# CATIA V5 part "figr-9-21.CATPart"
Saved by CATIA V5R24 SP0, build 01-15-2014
Part number: Part3
Bounding box of the stored display mesh (mm): x -112 to 0, y -101.683 to 104.654, z -80.304 to 44.557
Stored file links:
  D:\KAVITA\CATIA V5-6R2014 Project_ Kavita\CATIA V5-6R2014_partfiles\Partfiles\c09_catia_v5-6r2014_prt\figr-9-21.CATPart
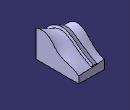
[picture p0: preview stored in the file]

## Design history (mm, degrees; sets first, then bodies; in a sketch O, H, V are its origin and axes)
Set1
  Plane1: type Offset, RefPlane yz-plane, Offset -112
  Plane2: type Offset, RefPlane yz-plane, Offset -63
  Plane3: type Normal, Curve Sketch4, RefPoint vertex of Sketch4
Body1 (main body)
  Sketch1 on yz-plane, origin (0, 0, 0), H (0, 1, 0), V (0, 0, 1)
    spline S1 through (-92.6897, 40.1119) (-30, 30) (10, -10) (60, -30) (97.3103, -50.3041)
    line L1 (97.3103, -50.3041) -> (97.3103, -80.3041)
    line L2 (97.3103, -80.3041) -> (-92.6897, -80.3041)
    line L3 (-92.6897, -80.3041) -> (-92.6897, 40.1119)
    point P3 (-92.6897, 40.1119)
    point P4 (97.3103, -50.3041)
    point P5 (-92.6897, 40.1119)
    point P6 (97.3103, -50.3041)
    vertical: L1 V, L3 V
    horizontal: L2 H
    coincidence: P5 P3, P6 P4
  Sketch2 on Plane1, origin (-112, 0, 0), H (0, 1, 0), V (0, 0, 1)
    spline S1 through (-90, -30) (-70, 10) (-20, 40) (40, 0) (100, -40)
    line L1 (100, -40) -> (100, -80)
    line L2 (100, -80) -> (-90, -80)
    line L3 (-90, -80) -> (-90, -30)
    point P3 (-90, -30)
    point P4 (100, -40)
    point P5 (40, 0)
    point P6 (-90, -30)
    point P7 (100, -40)
    coincidence: P5 H, P6 P3, P7 P4
    vertical: L1 V, L3 V
    horizontal: L2 H
  Loft1: Sections (Sketch1; Sketch2)
  Sketch3 on Plane3, origin (0, -40.1726, -44.9298), H (1, 0, 0), V (0, -0.7455, 0.6665)
    point P1 (-63, 68.4187)
    line L1 (-63, 68.4187) -> (-75.2117, 62.4925)
    line L2 (-75.2117, 62.4925) -> (-79.6266, 71.5898)
    line L3 (-79.6266, 71.5898) -> (-57.1205, 82.5119)
    line L4 (-57.1205, 82.5119) -> (-52.7056, 73.4145)
    point P5 (-52.7056, 73.4145)
    line L5 (-52.7056, 73.4145) -> (-63, 68.4187)
    reference projected point E1 (-63, 68.4187) from vertex of Sketch4
    perpendicularity: L2 L1
    parallelism: L3 L1, L4 L2, L5 L1
    coincidence: P5 L1, P1 E1
  Sketch4 on Plane2, origin (-63, 0, 0), H (0, 1, 0), V (0, 0, 1)
    intersected curve E1 from face of Loft1
  Rib1: profile Sketch3, centre curve Sketch4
